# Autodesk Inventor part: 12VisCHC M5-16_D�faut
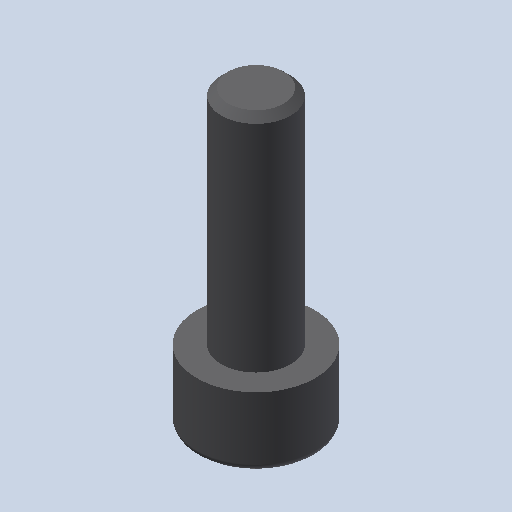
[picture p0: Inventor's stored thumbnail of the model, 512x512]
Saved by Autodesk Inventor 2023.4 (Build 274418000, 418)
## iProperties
Created: 2011-01
Part Number: 12VisCHC M5-16_D�faut
Document SubType Name: Modeling
Designer: eric
Density: 1 g/cm^3
Mass: 0.560016 g
Surface Area: 5.22208 cm^2
Volume: 0.560016 cm^3
Material: Générique
Appearance: Red
Author: eric
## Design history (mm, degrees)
feature "Base1"
node "Corps solides"
node "Corps surfaciques"
node "Solide1"
